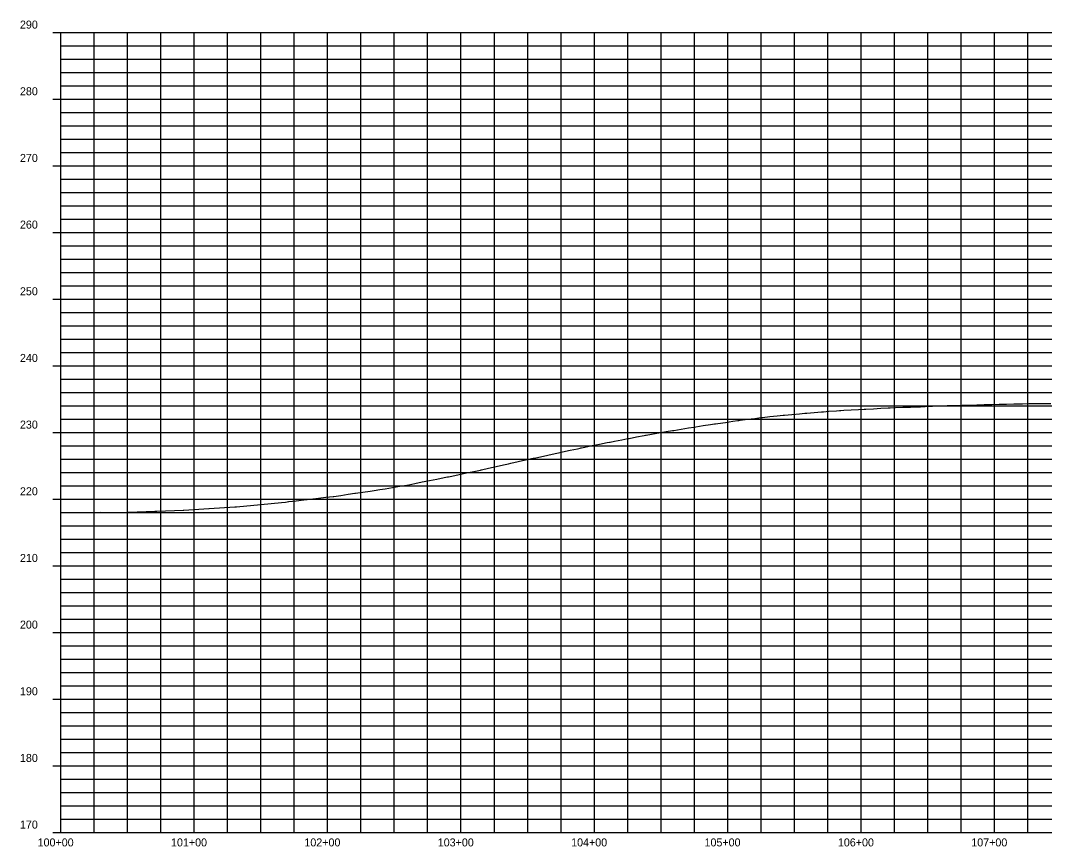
# Model space of a CAD drawing. Extents: x 921603 to 924670, y 1759276 to 1766491.
# Drawn here: x 921610 to 922377, y 1764922 to 1765541 of the extents above; entities that cross this region are included whole.
import ezdxf

# ---------------------------------------------------------------- set-up
doc = ezdxf.new("R2010")
doc.units = 0
for name, color, linetype in [('63', 7, 'Continuous'), ('R_Axis_Annotation', 7, 'Continuous'), ('R_Exist Surface', 7, 'Continuous'), ('R_Grid', 7, 'Continuous'), ('R_Grid Annot', 7, 'Continuous'), ('R_Grid_Minor', 7, 'Continuous')]:
    doc.layers.add(name, color=color, linetype=linetype)

msp = doc.modelspace()

# ---------------------------------------------------------------- linework, layer by layer
at = {"layer": 'R_Exist Surface'}
msp.add_lwpolyline([(921639.83, 1765172.26), (921649.13, 1765172.3), (921650.36, 1765172.3), (921669.43, 1765172.48), (921670.49, 1765172.46), (921689.68, 1765172.64), (921690.62, 1765172.63), (921710.35, 1765173.39), (921711.07, 1765173.39), (921711.78, 1765173.39), (921731.53, 1765174.16), (921732, 1765174.19), (921750.86, 1765175.34), (921751.11, 1765175.35), (921770.19, 1765176.51), (921770.23, 1765176.51), (921771.46, 1765176.63), (921789.83, 1765178.42), (921805.27, 1765179.91), (921808.27, 1765180.2), (921809.49, 1765180.35), (921810.63, 1765180.51), (921810.81, 1765180.53), (921816.36, 1765181.18), (921821.91, 1765181.82), (921826.95, 1765182.39), (921827.45, 1765182.46), (921828.7, 1765182.63), (921833, 1765183.12), (921838.55, 1765183.73), (921844.09, 1765184.34), (921844.4, 1765184.37), (921846.16, 1765184.68), (921849.64, 1765185.19), (921855.19, 1765186), (921860.34, 1765186.74), (921860.73, 1765186.81), (921862.38, 1765187.09), (921866.28, 1765187.64), (921871.83, 1765188.41), (921876.31, 1765189.03), (921877.37, 1765189.23), (921879, 1765189.53), (921882.92, 1765190.19), (921888.47, 1765191.11), (921894.01, 1765192.02), (921899.26, 1765192.87), (921899.56, 1765192.93), (921900.66, 1765193.16), (921905.11, 1765194.08), (921910.65, 1765195.22), (921914.93, 1765196.08), (921916.2, 1765196.33), (921921.75, 1765197.43), (921927.29, 1765198.52), (921929.68, 1765198.98), (921930.58, 1765199.16), (921931.79, 1765199.42), (921932.84, 1765199.65), (921938.39, 1765200.82), (921943.93, 1765201.98), (921949.48, 1765203.12), (921954.34, 1765204.11), (921955.03, 1765204.27), (921955.09, 1765204.28), (921960.57, 1765205.55), (921966.12, 1765206.81), (921971.67, 1765208.06), (921975.38, 1765208.89), (921977.21, 1765209.3), (921982.76, 1765210.54), (921988.31, 1765211.76), (921993.85, 1765212.97), (921995.85, 1765213.39), (921995.96, 1765213.42), (921996.05, 1765213.44), (921999.4, 1765214.19), (922004.95, 1765215.43), (922010.49, 1765216.65), (922012.82, 1765217.15), (922016.04, 1765217.85), (922021.59, 1765219.04), (922027.13, 1765220.21), (922029.23, 1765220.64), (922029.68, 1765220.74), (922030.23, 1765220.84), (922032.68, 1765221.35), (922038.23, 1765222.49), (922043.77, 1765223.61), (922049.32, 1765224.72), (922051.16, 1765225.08), (922051.72, 1765225.19), (922054.87, 1765225.81), (922060.41, 1765226.89), (922064.86, 1765227.75), (922065.96, 1765227.96), (922071.51, 1765229.01), (922077.05, 1765230.05), (922078.06, 1765230.23), (922078.55, 1765230.32), (922082.6, 1765231.05), (922088.15, 1765232.03), (922093.69, 1765232.99), (922098.38, 1765233.79), (922098.93, 1765233.89), (922099.24, 1765233.94), (922099.36, 1765233.96), (922104.79, 1765234.85), (922110.33, 1765235.74), (922114.64, 1765236.42), (922115.88, 1765236.62), (922121.43, 1765237.48), (922126.97, 1765238.33), (922129.97, 1765238.78), (922130.35, 1765238.83), (922130.77, 1765238.89), (922132.52, 1765239.15), (922138.07, 1765239.94), (922143.61, 1765240.72), (922147.49, 1765241.25), (922148.25, 1765241.36), (922149.16, 1765241.48), (922154.71, 1765242.23), (922160.25, 1765242.96), (922164.64, 1765243.52), (922165.2, 1765243.59), (922165.8, 1765243.65), (922171.35, 1765244.23), (922176.89, 1765244.8), (922181.48, 1765245.25), (922182.44, 1765245.35), (922187.99, 1765245.88), (922193.53, 1765246.4), (922197.53, 1765246.75), (922198.33, 1765246.83), (922199.08, 1765246.9), (922204.62, 1765247.35), (922210.17, 1765247.79), (922210.33, 1765247.8), (922211.74, 1765247.92), (922215.72, 1765248.22), (922221.26, 1765248.63), (922223.73, 1765248.8), (922224.74, 1765248.83), (922226.81, 1765248.97), (922232.36, 1765249.31), (922237.9, 1765249.64), (922242.09, 1765249.88), (922243.43, 1765249.91), (922243.45, 1765249.91), (922249, 1765250.21), (922254.54, 1765250.49), (922260.09, 1765250.76), (922260.45, 1765250.78), (922261.66, 1765250.89), (922265.64, 1765251.05), (922271.18, 1765251.27), (922276.73, 1765251.46), (922282.28, 1765251.64), (922283.5, 1765251.68), (922284.43, 1765251.69), (922287.82, 1765251.85), (922293.37, 1765252.11), (922298.92, 1765252.34), (922304.46, 1765252.56), (922304.95, 1765252.58), (922305.72, 1765252.59), (922310.01, 1765252.7), (922315.56, 1765252.83), (922321.1, 1765252.95), (922326.59, 1765253.04), (922326.65, 1765253.04), (922326.96, 1765253.05), (922332.2, 1765253.22), (922337.74, 1765253.38), (922343.29, 1765253.53), (922343.67, 1765253.54), (922348.84, 1765253.67), (922354.38, 1765253.78), (922359.93, 1765253.89), (922360.53, 1765253.9), (922360.75, 1765253.9), (922365.48, 1765253.97), (922371.02, 1765254.03), (922376.57, 1765254.09), (922382.12, 1765254.12)], dxfattribs=at)
at = {"layer": 'R_Grid'}
for p, q in [((921639.83, 1764932.26), (921639.83, 1765532.26)), ((921639.83, 1765532.26), (924639.83, 1765532.26)), ((921639.83, 1765532.26), (924639.83, 1765532.26)), ((921739.83, 1764932.26), (921739.83, 1765532.26)), ((921839.83, 1764932.26), (921839.83, 1765532.26)), ((921939.83, 1764932.26), (921939.83, 1765532.26)), ((922039.83, 1764932.26), (922039.83, 1765532.26)), ((922139.83, 1764932.26), (922139.83, 1765532.26)), ((922239.83, 1764932.26), (922239.83, 1765532.26)), ((922339.83, 1764932.26), (922339.83, 1765532.26)), ((921639.83, 1765482.26), (924639.83, 1765482.26)), ((921639.83, 1765432.26), (924639.83, 1765432.26)), ((921639.83, 1765382.26), (924639.83, 1765382.26)), ((921639.83, 1765332.26), (924639.83, 1765332.26)), ((921639.83, 1765282.26), (924639.83, 1765282.26)), ((921639.83, 1765232.26), (924639.83, 1765232.26)), ((921639.83, 1765182.26), (924639.83, 1765182.26)), ((921639.83, 1765132.26), (924639.83, 1765132.26)), ((921639.83, 1765082.26), (924639.83, 1765082.26)), ((921639.83, 1765032.26), (924639.83, 1765032.26)), ((921639.83, 1764982.26), (924639.83, 1764982.26)), ((921639.83, 1764932.26), (924639.83, 1764932.26))]:
    msp.add_line(p, q, dxfattribs=at)
at = {"layer": 'R_Grid Annot'}
for p, q in [((921633.83, 1765532.26), (921639.83, 1765532.26)), ((921633.83, 1765532.26), (921639.83, 1765532.26)), ((921639.83, 1765522.26), (921642.83, 1765522.26)), ((921639.83, 1765512.26), (921642.83, 1765512.26)), ((921639.83, 1765502.26), (921642.83, 1765502.26)), ((921639.83, 1765492.26), (921642.83, 1765492.26)), ((921633.83, 1765482.26), (921639.83, 1765482.26)), ((921639.83, 1765472.26), (921642.83, 1765472.26)), ((921639.83, 1765462.26), (921642.83, 1765462.26)), ((921639.83, 1765452.26), (921642.83, 1765452.26)), ((921639.83, 1765442.26), (921642.83, 1765442.26)), ((921633.83, 1765432.26), (921639.83, 1765432.26)), ((921639.83, 1765422.26), (921642.83, 1765422.26)), ((921639.83, 1765412.26), (921642.83, 1765412.26)), ((921639.83, 1765402.26), (921642.83, 1765402.26)), ((921639.83, 1765392.26), (921642.83, 1765392.26)), ((921633.83, 1765382.26), (921639.83, 1765382.26)), ((921639.83, 1765372.26), (921642.83, 1765372.26)), ((921639.83, 1765362.26), (921642.83, 1765362.26)), ((921639.83, 1765352.26), (921642.83, 1765352.26)), ((921639.83, 1765342.26), (921642.83, 1765342.26)), ((921633.83, 1765332.26), (921639.83, 1765332.26)), ((921639.83, 1765322.26), (921642.83, 1765322.26)), ((921639.83, 1765312.26), (921642.83, 1765312.26)), ((921639.83, 1765302.26), (921642.83, 1765302.26)), ((921639.83, 1765292.26), (921642.83, 1765292.26)), ((921633.83, 1765282.26), (921639.83, 1765282.26)), ((921639.83, 1765272.26), (921642.83, 1765272.26)), ((921639.83, 1765262.26), (921642.83, 1765262.26)), ((921639.83, 1765252.26), (921642.83, 1765252.26)), ((921639.83, 1765242.26), (921642.83, 1765242.26)), ((921633.83, 1765232.26), (921639.83, 1765232.26)), ((921639.83, 1765222.26), (921642.83, 1765222.26)), ((921639.83, 1765212.26), (921642.83, 1765212.26)), ((921639.83, 1765202.26), (921642.83, 1765202.26)), ((921639.83, 1765192.26), (921642.83, 1765192.26)), ((921633.83, 1765182.26), (921639.83, 1765182.26)), ((921639.83, 1765172.26), (921642.83, 1765172.26)), ((921639.83, 1765162.26), (921642.83, 1765162.26)), ((921639.83, 1765152.26), (921642.83, 1765152.26)), ((921639.83, 1765142.26), (921642.83, 1765142.26)), ((921633.83, 1765132.26), (921639.83, 1765132.26)), ((921639.83, 1765122.26), (921642.83, 1765122.26)), ((921639.83, 1765112.26), (921642.83, 1765112.26)), ((921639.83, 1765102.26), (921642.83, 1765102.26)), ((921639.83, 1765092.26), (921642.83, 1765092.26)), ((921633.83, 1765082.26), (921639.83, 1765082.26)), ((921639.83, 1765072.26), (921642.83, 1765072.26)), ((921639.83, 1765062.26), (921642.83, 1765062.26)), ((921639.83, 1765052.26), (921642.83, 1765052.26)), ((921639.83, 1765042.26), (921642.83, 1765042.26)), ((921633.83, 1765032.26), (921639.83, 1765032.26)), ((921639.83, 1765022.26), (921642.83, 1765022.26)), ((921639.83, 1765012.26), (921642.83, 1765012.26)), ((921639.83, 1765002.26), (921642.83, 1765002.26)), ((921639.83, 1764992.26), (921642.83, 1764992.26)), ((921633.83, 1764982.26), (921639.83, 1764982.26)), ((921639.83, 1764972.26), (921642.83, 1764972.26)), ((921639.83, 1764962.26), (921642.83, 1764962.26)), ((921639.83, 1764952.26), (921642.83, 1764952.26)), ((921639.83, 1764942.26), (921642.83, 1764942.26)), ((921633.83, 1764932.26), (921639.83, 1764932.26))]:
    msp.add_line(p, q, dxfattribs=at)
at = {"layer": 'R_Grid_Minor'}
for p, q in [((921664.83, 1764932.26), (921664.83, 1765532.26)), ((921689.83, 1764932.26), (921689.83, 1765532.26)), ((921714.83, 1764932.26), (921714.83, 1765532.26)), ((921764.83, 1764932.26), (921764.83, 1765532.26)), ((921789.83, 1764932.26), (921789.83, 1765532.26)), ((921814.83, 1764932.26), (921814.83, 1765532.26)), ((921864.83, 1764932.26), (921864.83, 1765532.26)), ((921889.83, 1764932.26), (921889.83, 1765532.26)), ((921914.83, 1764932.26), (921914.83, 1765532.26)), ((921964.83, 1764932.26), (921964.83, 1765532.26)), ((921989.83, 1764932.26), (921989.83, 1765532.26)), ((922014.83, 1764932.26), (922014.83, 1765532.26)), ((922064.83, 1764932.26), (922064.83, 1765532.26)), ((922089.83, 1764932.26), (922089.83, 1765532.26)), ((922114.83, 1764932.26), (922114.83, 1765532.26)), ((922164.83, 1764932.26), (922164.83, 1765532.26)), ((922189.83, 1764932.26), (922189.83, 1765532.26)), ((922214.83, 1764932.26), (922214.83, 1765532.26)), ((922264.83, 1764932.26), (922264.83, 1765532.26)), ((922289.83, 1764932.26), (922289.83, 1765532.26)), ((922314.83, 1764932.26), (922314.83, 1765532.26)), ((922364.83, 1764932.26), (922364.83, 1765532.26)), ((921639.83, 1765522.26), (924639.83, 1765522.26)), ((921639.83, 1765512.26), (924639.83, 1765512.26)), ((921639.83, 1765502.26), (924639.83, 1765502.26)), ((921639.83, 1765492.26), (924639.83, 1765492.26)), ((921639.83, 1765472.26), (924639.83, 1765472.26)), ((921639.83, 1765462.26), (924639.83, 1765462.26)), ((921639.83, 1765452.26), (924639.83, 1765452.26)), ((921639.83, 1765442.26), (924639.83, 1765442.26)), ((921639.83, 1765422.26), (924639.83, 1765422.26)), ((921639.83, 1765412.26), (924639.83, 1765412.26)), ((921639.83, 1765402.26), (924639.83, 1765402.26)), ((921639.83, 1765392.26), (924639.83, 1765392.26)), ((921639.83, 1765372.26), (924639.83, 1765372.26)), ((921639.83, 1765362.26), (924639.83, 1765362.26)), ((921639.83, 1765352.26), (924639.83, 1765352.26)), ((921639.83, 1765342.26), (924639.83, 1765342.26)), ((921639.83, 1765322.26), (924639.83, 1765322.26)), ((921639.83, 1765312.26), (924639.83, 1765312.26)), ((921639.83, 1765302.26), (924639.83, 1765302.26)), ((921639.83, 1765292.26), (924639.83, 1765292.26)), ((921639.83, 1765272.26), (924639.83, 1765272.26)), ((921639.83, 1765262.26), (924639.83, 1765262.26)), ((921639.83, 1765252.26), (924639.83, 1765252.26)), ((921639.83, 1765242.26), (924639.83, 1765242.26)), ((921639.83, 1765222.26), (924639.83, 1765222.26)), ((921639.83, 1765212.26), (924639.83, 1765212.26)), ((921639.83, 1765202.26), (924639.83, 1765202.26)), ((921639.83, 1765192.26), (924639.83, 1765192.26)), ((921639.83, 1765172.26), (924639.83, 1765172.26)), ((921639.83, 1765162.26), (924639.83, 1765162.26)), ((921639.83, 1765152.26), (924639.83, 1765152.26)), ((921639.83, 1765142.26), (924639.83, 1765142.26)), ((921639.83, 1765122.26), (924639.83, 1765122.26)), ((921639.83, 1765112.26), (924639.83, 1765112.26)), ((921639.83, 1765102.26), (924639.83, 1765102.26)), ((921639.83, 1765092.26), (924639.83, 1765092.26)), ((921639.83, 1765072.26), (924639.83, 1765072.26)), ((921639.83, 1765062.26), (924639.83, 1765062.26)), ((921639.83, 1765052.26), (924639.83, 1765052.26)), ((921639.83, 1765042.26), (924639.83, 1765042.26)), ((921639.83, 1765022.26), (924639.83, 1765022.26)), ((921639.83, 1765012.26), (924639.83, 1765012.26)), ((921639.83, 1765002.26), (924639.83, 1765002.26)), ((921639.83, 1764992.26), (924639.83, 1764992.26)), ((921639.83, 1764972.26), (924639.83, 1764972.26)), ((921639.83, 1764962.26), (924639.83, 1764962.26)), ((921639.83, 1764952.26), (924639.83, 1764952.26)), ((921639.83, 1764942.26), (924639.83, 1764942.26))]:
    msp.add_line(p, q, dxfattribs=at)

# ---------------------------------------------------------------- texts
at = {"layer": '63'}
msp.add_text('-', height=0.0001, dxfattribs=at).set_placement((921639.83, 1764932.26))
at = {"layer": 'R_Axis_Annotation'}
for s, p in [('290', (921609.16, 1765535.26)), ('290', (921609.16, 1765535.26)), ('280', (921609.16, 1765485.26)), ('270', (921609.16, 1765435.26)), ('260', (921609.16, 1765385.26)), ('250', (921609.16, 1765335.26)), ('240', (921609.16, 1765285.26)), ('230', (921609.16, 1765235.26)), ('220', (921609.16, 1765185.26)), ('210', (921609.16, 1765135.26)), ('200', (921609.16, 1765085.26)), ('190', (921609.16, 1765035.26)), ('180', (921609.16, 1764985.26)), ('170', (921609.16, 1764935.26)), ('100+00', (921622.42, 1764921.91)), ('101+00', (921722.42, 1764921.91)), ('102+00', (921822.42, 1764921.91)), ('103+00', (921922.42, 1764921.91)), ('104+00', (922022.42, 1764921.91)), ('105+00', (922122.42, 1764921.91)), ('106+00', (922222.42, 1764921.91)), ('107+00', (922322.42, 1764921.91))]:
    msp.add_text(s, height=6, dxfattribs=at).set_placement(p)

doc.saveas('drawing.dxf')
